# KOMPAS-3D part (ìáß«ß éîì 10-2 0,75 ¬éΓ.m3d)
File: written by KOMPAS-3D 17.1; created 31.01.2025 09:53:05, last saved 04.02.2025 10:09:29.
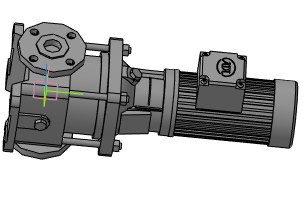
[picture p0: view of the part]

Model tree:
1. Операция без истории:3  (labels: Насос ВМН 10-2 0.75 кВт)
